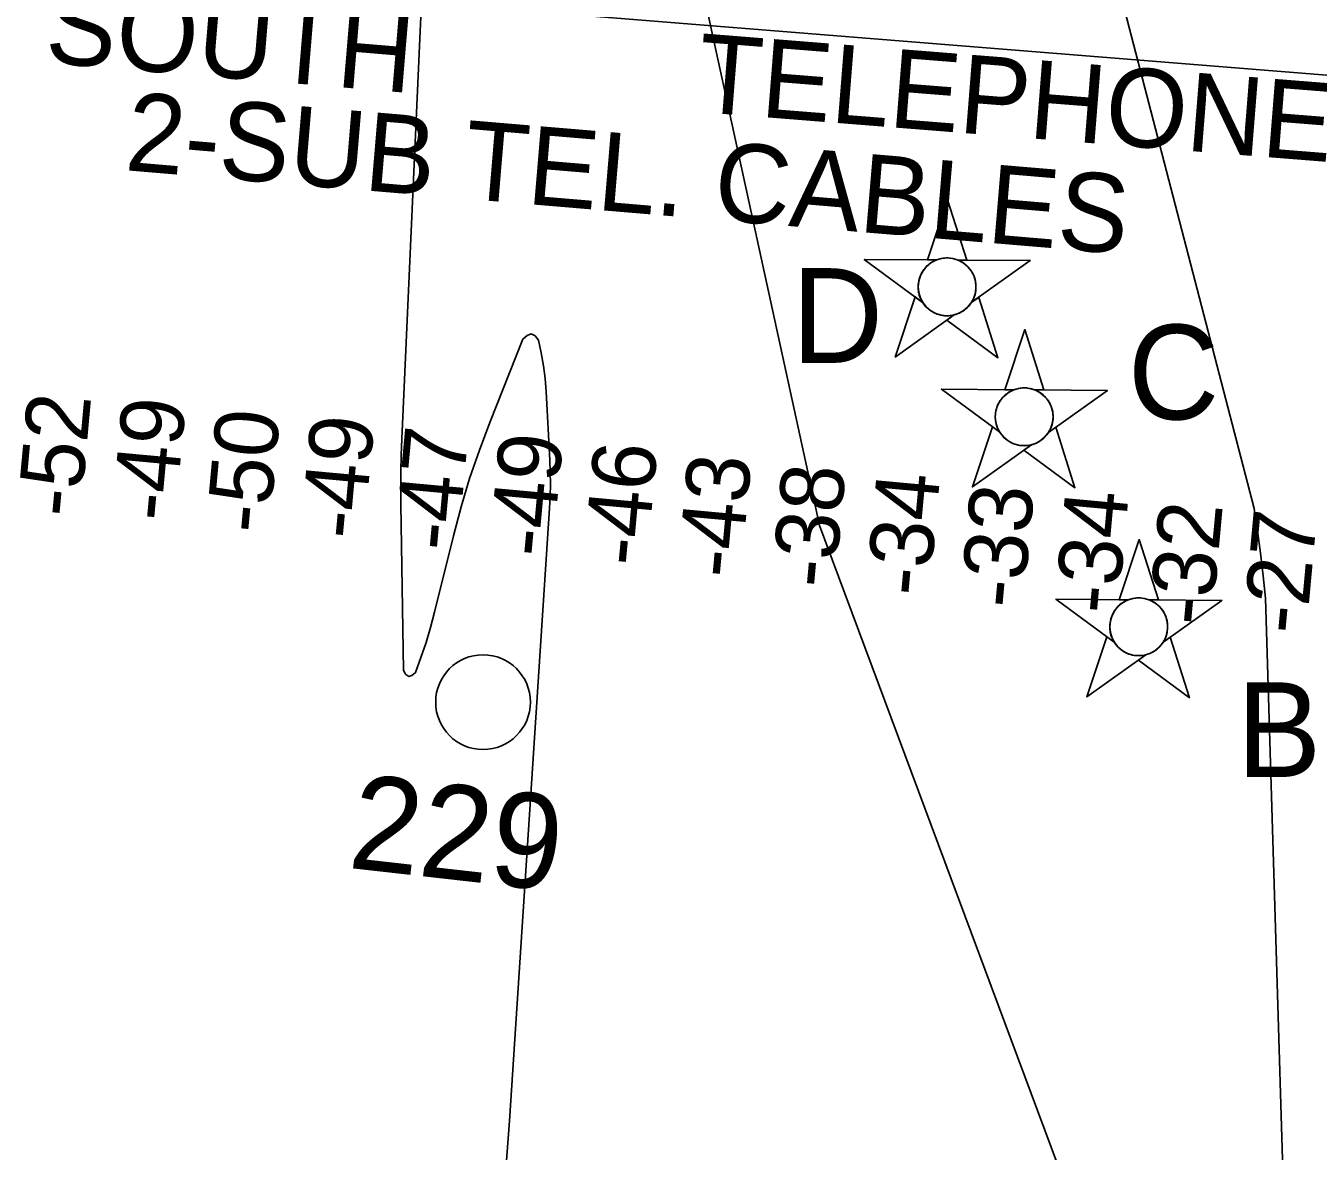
# Model space of a CAD drawing. Extents: x 3297716 to 3335574, y 688621 to 713991.
# Drawn here: x 3323333 to 3324697, y 703651 to 704839 of the extents above; entities that cross this region are included whole.
import ezdxf

# ---------------------------------------------------------------- set-up
doc = ezdxf.new("R2010")
doc.units = 0
for name, color, linetype in [('V-CHAN-NAID', 7, 'Continuous'), ('V-RIVR-IDEN', 7, 'Continuous'), ('V-RIVR-MILE', 7, 'Continuous'), ('V-RIVR-RANG', 7, 'Continuous'), ('V-TOPO-DPTH', 7, 'Continuous'), ('V-TOPO-MAJR', 7, 'Continuous'), ('V-TOPO-MINR', 7, 'Continuous'), ('V-UTIL-IDEN', 7, 'Continuous'), ('V-UTIL-LINE', 7, 'Continuous')]:
    doc.layers.add(name, color=color, linetype=linetype)

msp = doc.modelspace()

# ---------------------------------------------------------------- linework, layer by layer
at = {"layer": 'V-CHAN-NAID'}
for points in [[(3324294.4, 704592.2), (3324284.8, 704592.3), (3324305.9, 704655.7), (3324326.2, 704592), (3324316.6, 704592), (3324315, 704592.6), (3324312.9, 704593.2), (3324310.9, 704593.7), (3324308.8, 704594), (3324307.7, 704594.1), (3324306.1, 704594.2), (3324304.4, 704594.2), (3324303, 704594.1), (3324301.1, 704593.9), (3324299.8, 704593.7), (3324298, 704593.3), (3324296.5, 704592.9), (3324295.4, 704592.6)], [(3324294.4, 704592.2), (3324217.9, 704592.7), (3324279.5, 704547.3), (3324278.4, 704549.2), (3324277.6, 704550.9), (3324276.7, 704552.8), (3324276, 704554.9), (3324275.7, 704556.2), (3324275.3, 704557.8), (3324275.1, 704559.3), (3324274.9, 704560.9), (3324274.8, 704562.6), (3324274.8, 704564.2), (3324274.9, 704566.3), (3324275, 704567.9), (3324275.4, 704570.1), (3324275.9, 704572), (3324276.5, 704573.9), (3324277.2, 704575.6), (3324277.9, 704577.2), (3324278.7, 704578.7), (3324279.8, 704580.4), (3324280.8, 704581.9), (3324281.8, 704583.2), (3324282.8, 704584.3), (3324284.1, 704585.7), (3324285.2, 704586.6), (3324286.9, 704588), (3324288.1, 704588.9), (3324289.8, 704590), (3324291.5, 704590.9), (3324293, 704591.6)], [(3324316.6, 704592), (3324393.1, 704591.5), (3324330.9, 704547), (3324331.8, 704548.5), (3324332.8, 704550.3), (3324333.5, 704551.9), (3324334.2, 704553.8), (3324334.8, 704555.6), (3324335.2, 704557.3), (3324335.5, 704559.3), (3324335.7, 704560.9), (3324335.8, 704563.1), (3324335.8, 704565.1), (3324335.6, 704567.3), (3324335.3, 704569.1), (3324334.9, 704571.3), (3324334.2, 704573.5), (3324333.5, 704575.5), (3324332.8, 704576.9), (3324331.8, 704578.8), (3324330.7, 704580.5), (3324329.5, 704582.2), (3324328.3, 704583.8), (3324327, 704585.1), (3324325.4, 704586.7), (3324323.6, 704588.1), (3324321.9, 704589.3), (3324320.1, 704590.4), (3324318.6, 704591.2)], [(3324312.8, 704534.1), (3324250.6, 704489.5), (3324271.8, 704553), (3324279.5, 704547.3), (3324280.1, 704546.4), (3324281.5, 704544.5), (3324282.7, 704543.1), (3324284.2, 704541.6), (3324285.6, 704540.3), (3324287, 704539.2), (3324288.4, 704538.2), (3324290.1, 704537.2), (3324291.8, 704536.3), (3324293.6, 704535.4), (3324295, 704534.9), (3324296.7, 704534.4), (3324298.9, 704533.8), (3324300.4, 704533.5), (3324302.5, 704533.2), (3324304, 704533.1), (3324305.9, 704533.1), (3324307.5, 704533.2), (3324309.3, 704533.4), (3324311.2, 704533.7)], [(3324330.9, 704547), (3324338.7, 704552.6), (3324358.9, 704488.8), (3324305, 704528.5), (3324312.8, 704534.1), (3324314.5, 704534.5), (3324316.1, 704535.1), (3324318.3, 704536), (3324320, 704536.9), (3324321.9, 704538), (3324323.6, 704539.2), (3324325.2, 704540.5), (3324326.5, 704541.6), (3324327.8, 704543.1), (3324329, 704544.5), (3324330.2, 704545.9)], [(3324375.9, 704455), (3324366.3, 704455.1), (3324387.4, 704518.6), (3324407.6, 704454.8), (3324398, 704454.9), (3324396.5, 704455.4), (3324394.4, 704456.1), (3324392.3, 704456.5), (3324390.3, 704456.8), (3324389.1, 704456.9), (3324387.6, 704457), (3324385.9, 704457), (3324384.5, 704456.9), (3324382.6, 704456.7), (3324381.2, 704456.5), (3324379.4, 704456.1), (3324377.9, 704455.7), (3324376.9, 704455.4)], [(3324375.9, 704455), (3324299.4, 704455.6), (3324360.9, 704410.2), (3324359.8, 704412.1), (3324359, 704413.7), (3324358.2, 704415.7), (3324357.5, 704417.7), (3324357.1, 704419), (3324356.8, 704420.7), (3324356.5, 704422.1), (3324356.3, 704423.7), (3324356.2, 704425.4), (3324356.2, 704427), (3324356.3, 704429.1), (3324356.5, 704430.7), (3324356.9, 704432.9), (3324357.4, 704434.8), (3324358, 704436.7), (3324358.6, 704438.4), (3324359.4, 704440), (3324360.2, 704441.5), (3324361.2, 704443.3), (3324362.3, 704444.7), (3324363.3, 704446), (3324364.3, 704447.1), (3324365.6, 704448.5), (3324366.6, 704449.5), (3324368.3, 704450.8), (3324369.6, 704451.7), (3324371.2, 704452.8), (3324373, 704453.7), (3324374.4, 704454.4)], [(3324398, 704454.9), (3324474.5, 704454.3), (3324412.3, 704409.8), (3324413.2, 704411.3), (3324414.2, 704413.1), (3324414.9, 704414.7), (3324415.7, 704416.7), (3324416.2, 704418.4), (3324416.6, 704420.1), (3324417, 704422.1), (3324417.2, 704423.7), (3324417.3, 704425.9), (3324417.3, 704427.9), (3324417.1, 704430.2), (3324416.8, 704431.9), (3324416.3, 704434.1), (3324415.7, 704436.3), (3324414.9, 704438.3), (3324414.3, 704439.7), (3324413.3, 704441.6), (3324412.2, 704443.4), (3324411, 704445.1), (3324409.7, 704446.6), (3324408.5, 704448), (3324406.8, 704449.5), (3324405.1, 704450.9), (3324403.4, 704452.1), (3324401.5, 704453.2), (3324400, 704454)], [(3324394.3, 704396.9), (3324332.1, 704352.4), (3324353.2, 704415.8), (3324360.9, 704410.2), (3324361.6, 704409.2), (3324363, 704407.3), (3324364.2, 704405.9), (3324365.6, 704404.4), (3324367, 704403.2), (3324368.5, 704402), (3324369.9, 704401), (3324371.6, 704400), (3324373.3, 704399.1), (3324375.1, 704398.3), (3324376.5, 704397.7), (3324378.1, 704397.2), (3324380.4, 704396.6), (3324381.9, 704396.3), (3324383.9, 704396.1), (3324385.5, 704396), (3324387.3, 704395.9), (3324389, 704396), (3324390.7, 704396.2), (3324392.6, 704396.5)], [(3324412.3, 704409.8), (3324420.1, 704415.4), (3324440.3, 704351.6), (3324386.5, 704391.3), (3324394.3, 704396.9), (3324396, 704397.4), (3324397.6, 704397.9), (3324399.7, 704398.8), (3324401.5, 704399.7), (3324403.3, 704400.8), (3324405.1, 704402), (3324406.6, 704403.3), (3324407.9, 704404.5), (3324409.3, 704405.9), (3324410.5, 704407.3), (3324411.6, 704408.7)], [(3324496.7, 704233.3), (3324487.1, 704233.4), (3324508.2, 704296.9), (3324528.4, 704233.1), (3324518.9, 704233.2), (3324517.3, 704233.7), (3324515.2, 704234.4), (3324513.1, 704234.8), (3324511.1, 704235.1), (3324509.9, 704235.2), (3324508.4, 704235.3), (3324506.7, 704235.3), (3324505.3, 704235.2), (3324503.4, 704235), (3324502, 704234.8), (3324500.3, 704234.4), (3324498.7, 704234), (3324497.7, 704233.7)], [(3324496.7, 704233.3), (3324420.2, 704233.9), (3324481.8, 704188.5), (3324480.6, 704190.4), (3324479.8, 704192), (3324479, 704194), (3324478.3, 704196), (3324477.9, 704197.3), (3324477.6, 704199), (3324477.3, 704200.4), (3324477.2, 704202), (3324477, 704203.7), (3324477, 704205.3), (3324477.1, 704207.4), (3324477.3, 704209), (3324477.7, 704211.2), (3324478.2, 704213.1), (3324478.8, 704215), (3324479.5, 704216.7), (3324480.2, 704218.3), (3324481, 704219.8), (3324482.1, 704221.6), (3324483.1, 704223), (3324484.1, 704224.3), (3324485.1, 704225.5), (3324486.4, 704226.8), (3324487.4, 704227.8), (3324489.2, 704229.2), (3324490.4, 704230), (3324492.1, 704231.1), (3324493.8, 704232), (3324495.2, 704232.7)], [(3324518.9, 704233.2), (3324595.4, 704232.6), (3324533.1, 704188.1), (3324534.1, 704189.6), (3324535, 704191.4), (3324535.8, 704193), (3324536.5, 704195), (3324537, 704196.8), (3324537.4, 704198.4), (3324537.8, 704200.4), (3324538, 704202), (3324538.1, 704204.2), (3324538.1, 704206.2), (3324537.9, 704208.5), (3324537.6, 704210.2), (3324537.1, 704212.5), (3324536.5, 704214.6), (3324535.7, 704216.6), (3324535.1, 704218), (3324534.1, 704219.9), (3324533, 704221.7), (3324531.8, 704223.4), (3324530.5, 704224.9), (3324529.3, 704226.3), (3324527.6, 704227.8), (3324525.9, 704229.2), (3324524.2, 704230.4), (3324522.3, 704231.5), (3324520.9, 704232.3)], [(3324515.1, 704175.2), (3324452.9, 704130.7), (3324474, 704194.2), (3324481.8, 704188.5), (3324482.4, 704187.5), (3324483.8, 704185.6), (3324485, 704184.2), (3324486.5, 704182.7), (3324487.8, 704181.5), (3324489.3, 704180.3), (3324490.7, 704179.3), (3324492.4, 704178.3), (3324494.1, 704177.4), (3324495.9, 704176.6), (3324497.3, 704176), (3324499, 704175.5), (3324501.2, 704174.9), (3324502.7, 704174.6), (3324504.7, 704174.4), (3324506.3, 704174.3), (3324508.1, 704174.2), (3324509.8, 704174.3), (3324511.5, 704174.5), (3324513.4, 704174.8)], [(3324533.1, 704188.1), (3324540.9, 704193.7), (3324561.2, 704129.9), (3324507.3, 704169.6), (3324515.1, 704175.2), (3324516.8, 704175.7), (3324518.4, 704176.2), (3324520.6, 704177.1), (3324522.3, 704178), (3324524.2, 704179.1), (3324525.9, 704180.4), (3324527.4, 704181.6), (3324528.7, 704182.8), (3324530.1, 704184.2), (3324531.3, 704185.6), (3324532.4, 704187.1)]]:
    msp.add_lwpolyline(points, close=True, dxfattribs=at)
for centre in [(3324305.3, 704563.7), (3324386.7, 704426.5), (3324507.6, 704204.8)]:
    msp.add_circle(centre, 30.5, dxfattribs=at)
at = {"layer": 'V-RIVR-MILE'}
msp.add_circle((3323815.5, 704125.2), 50, dxfattribs=at)
at = {"layer": 'V-TOPO-DPTH'}
for points in [[(3324569.8, 703240.9), (3324169.6, 704314.5), (3324168.6, 704321.7), (3323983.6, 705170.6), (3323983.1, 705174.7), (3323982.1, 705184.8), (3323981.1, 705194), (3323980.1, 705203.2), (3323979.1, 705212.4), (3323978, 705221.6), (3323769, 705981.7), (3323767.3, 705987.7), (3323766.1, 705994), (3323756.6, 706063.9), (3323755, 706076.7), (3323753.8, 706089.6), (3323753.1, 706102.5), (3323752.7, 706115.5), (3323741, 706892.8)], [(3323741, 706892.8), (3323752.7, 706115.5), (3323753.1, 706102.5), (3323753.8, 706089.6), (3323755, 706076.7), (3323756.6, 706063.9), (3323766.1, 705994), (3323767.3, 705987.7), (3323769, 705981.7), (3323978, 705221.6), (3323979.1, 705212.4), (3323980.1, 705203.2), (3323981.1, 705194), (3323982.1, 705184.8), (3323983.1, 705174.7), (3323983.6, 705170.6), (3324168.6, 704321.7), (3324169.6, 704314.5), (3324569.8, 703240.9)], [(3324416.3, 705150.6), (3324629.6, 704329.8), (3324633, 704306.1), (3324636.1, 704282.5), (3324639, 704258.7), (3324641.6, 704235), (3324671.9, 703224.1)], [(3324507, 704959.4), (3324504.1, 704963.3), (3324468.3, 704950.6), (3324470.1, 704943.5), (3324629.6, 704329.8), (3324633, 704306.1), (3324636.1, 704282.5), (3324639, 704258.7), (3324641.6, 704235), (3324671.9, 703224.1)]]:
    msp.add_lwpolyline(points, dxfattribs=at)
at = {"layer": 'V-TOPO-MAJR'}
msp.add_lwpolyline([(3323751.2, 704880.8), (3323729.7, 704403.1), (3323729.1, 704385.9), (3323728.7, 704368.7), (3323728.6, 704351.5), (3323728.7, 704334.2), (3323731.6, 704158.7), (3323734.1, 704154.5), (3323737, 704152.3), (3323740.4, 704153.3), (3323744.2, 704156.4), (3323750, 704172.2), (3323755.3, 704188.1), (3323760, 704204.1), (3323764.3, 704220.3), (3323784.2, 704300.9), (3323792.4, 704331.3), (3323801.3, 704361.4), (3323811.6, 704391.1), (3323822.6, 704420.5), (3323857.6, 704508.4), (3323862.1, 704512.4), (3323866.4, 704513.9), (3323870.4, 704511.8), (3323874.2, 704507.3), (3323877, 704493.9), (3323879.4, 704480.4), (3323881, 704466.8), (3323882.1, 704453.2), (3323886, 704380.7), (3323886.4, 704368), (3323886.6, 704355.4), (3323886.3, 704342.7), (3323885.7, 704330.1), (3323843.4, 703683.3), (3323838.2, 703613)], dxfattribs=at)
at = {"layer": 'V-TOPO-MINR'}
for points in [[(3323741, 706892.8), (3323752.7, 706115.5), (3323753.1, 706102.5), (3323753.8, 706089.6), (3323755, 706076.7), (3323756.6, 706063.9), (3323766.1, 705994), (3323767.3, 705987.7), (3323769, 705981.7), (3323978, 705221.6), (3323979.1, 705212.4), (3323980.1, 705203.2), (3323981.1, 705194), (3323982.1, 705184.8), (3323983.1, 705174.7), (3323983.6, 705170.6), (3324168.6, 704321.7), (3324169.6, 704314.5), (3324569.8, 703240.9)], [(3324671.9, 703224.1), (3324641.6, 704235), (3324639, 704258.7), (3324636.1, 704282.5), (3324633, 704306.1), (3324629.6, 704329.8), (3324416.3, 705150.6)]]:
    msp.add_lwpolyline(points, dxfattribs=at)
at = {"layer": 'V-UTIL-LINE'}
msp.add_line((3325501.8, 704723.3), (3322213.6, 704987.6), dxfattribs=at)

# ---------------------------------------------------------------- texts
at = {"layer": 'V-CHAN-NAID'}
for s, p in [('D', (3324141.3, 704483.4)), ('C', (3324496.1, 704423.7)), ('B', (3324611.1, 704046.2))]:
    msp.add_text(s, height=100, dxfattribs=at).set_placement(p)
at = {"layer": 'V-RIVR-IDEN'}
msp.add_text('229', height=100, rotation=353.563, dxfattribs=at).set_placement((3323671.6, 703950.4))
at = {"layer": 'V-RIVR-RANG'}
for s, p in [('-52', (3323390.1, 704319)), ('-49', (3323490.1, 704314.6)), ('-50', (3323589.4, 704302)), ('-49', (3323689.2, 704295.7)), ('-47', (3323788.5, 704283.4)), ('-49', (3323888.3, 704276.9)), ('-46', (3323987.9, 704267.3)), ('-43', (3324087.1, 704254.7)), ('-38', (3324186.6, 704244.2)), ('-34', (3324286.2, 704235.6)), ('-33', (3324385.5, 704222.8)), ('-34', (3324485.3, 704216.8)), ('-32', (3324584.6, 704204.5)), ('-27', (3324684.2, 704195.6))]:
    msp.add_text(s, height=67, rotation=84.7446, dxfattribs=at).set_placement(p)
at = {"layer": 'V-UTIL-IDEN'}
for s, rotation, p in [('BELL SOUTH', 355.2254, (3323050.6, 704825.7)), ('TELEPHONE. CO.', 355.4566, (3324039.5, 704748.6)), ('2-SUB TEL. CABLES', 355.1953, (3323436.4, 704686.9))]:
    msp.add_text(s, height=83, rotation=rotation, dxfattribs=at).set_placement(p)

doc.saveas('drawing.dxf')
